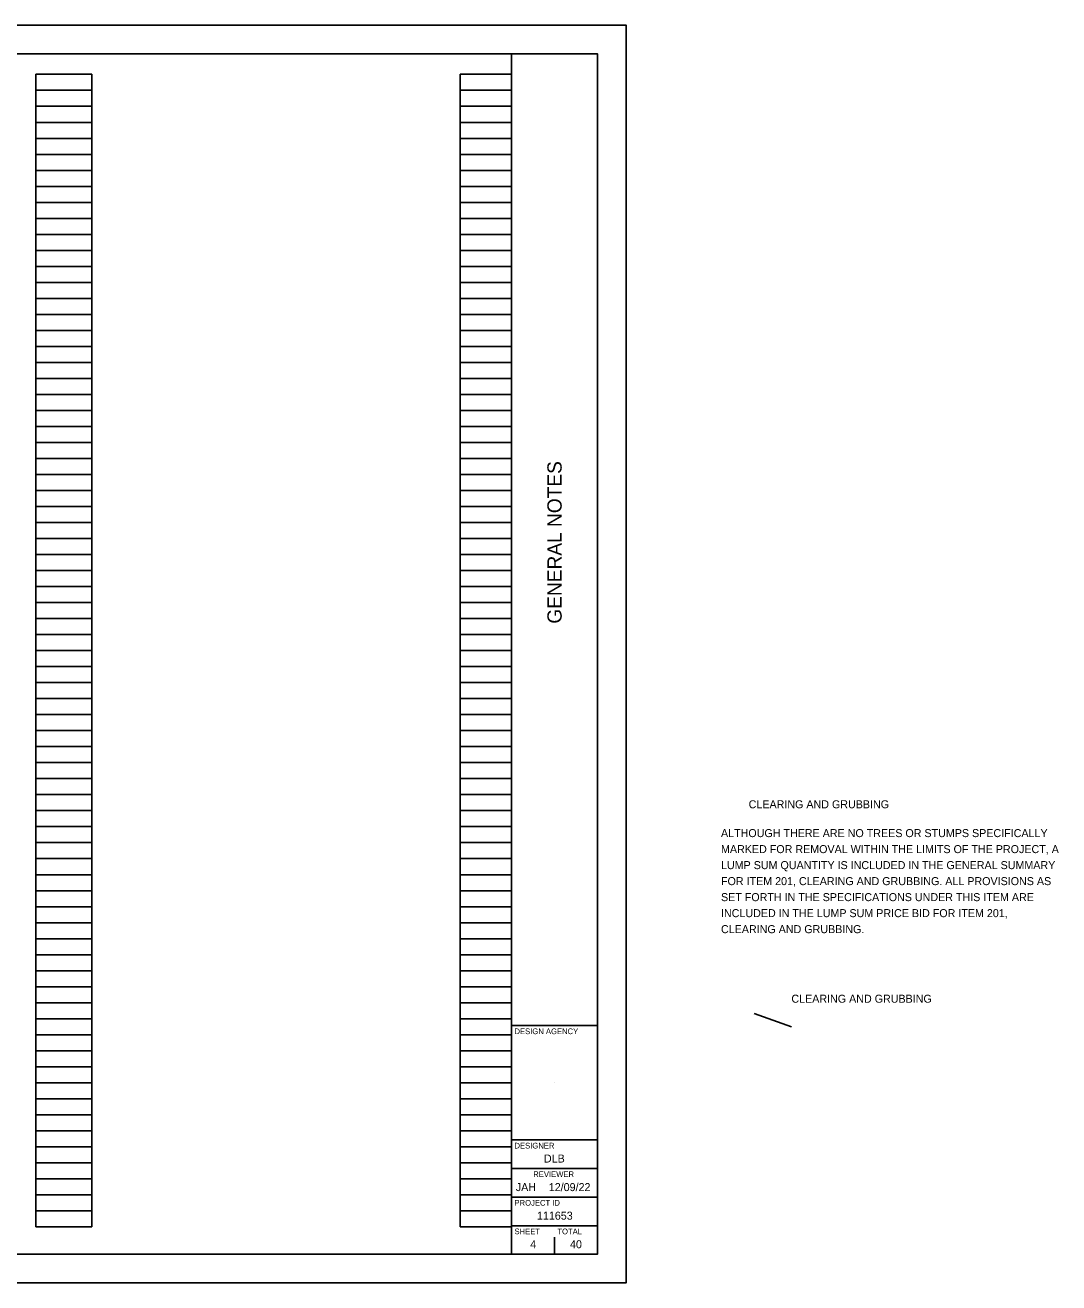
# Model space of a CAD drawing. Extents: x 0 to 41.6, y 0 to 22.
# Drawn here: x 23.49 to 41.57, y 0 to 22 of the extents above; entities that cross this region are included whole.
import ezdxf

# ---------------------------------------------------------------- set-up
doc = ezdxf.new("R2010")
doc.units = 0
for name, color, linetype in [('SC_Scratch2', 7, 'Continuous'), ('SH_Border', 7, 'Continuous'), ('SH_Cut_Line', 7, 'Continuous'), ('SH_Data', 7, 'Continuous'), ('SH_Text', 7, 'Continuous')]:
    doc.layers.add(name, color=color, linetype=linetype)

msp = doc.modelspace()

# ---------------------------------------------------------------- linework, layer by layer
at = {"layer": 'SC_Scratch2'}
for p, q in [((23.68, 0.98), (23.68, 21.14)), ((23.68, 21.14), (24.66, 21.14)), ((24.66, 0.98), (24.66, 21.14)), ((31.1, 0.98), (31.1, 21.14)), ((31.1, 21.14), (32, 21.14)), ((32, 0.98), (32, 21.14)), ((23.68, 20.86), (24.66, 20.86)), ((31.1, 20.86), (32, 20.86)), ((23.68, 20.58), (24.66, 20.58)), ((31.1, 20.58), (32, 20.58)), ((23.68, 20.3), (24.66, 20.3)), ((31.1, 20.3), (32, 20.3)), ((23.68, 20.02), (24.66, 20.02)), ((31.1, 20.02), (32, 20.02)), ((23.68, 19.74), (24.66, 19.74)), ((31.1, 19.74), (32, 19.74)), ((23.68, 19.46), (24.66, 19.46)), ((31.1, 19.46), (32, 19.46)), ((23.68, 19.18), (24.66, 19.18)), ((31.1, 19.18), (32, 19.18)), ((23.68, 18.9), (24.66, 18.9)), ((31.1, 18.9), (32, 18.9)), ((23.68, 18.62), (24.66, 18.62)), ((31.1, 18.62), (32, 18.62)), ((23.68, 18.34), (24.66, 18.34)), ((31.1, 18.34), (32, 18.34)), ((23.68, 18.06), (24.66, 18.06)), ((31.1, 18.06), (32, 18.06)), ((23.68, 17.78), (24.66, 17.78)), ((31.1, 17.78), (32, 17.78)), ((23.68, 17.5), (24.66, 17.5)), ((31.1, 17.5), (32, 17.5)), ((23.68, 17.22), (24.66, 17.22)), ((31.1, 17.22), (32, 17.22)), ((23.68, 16.94), (24.66, 16.94)), ((31.1, 16.94), (32, 16.94)), ((23.68, 16.66), (24.66, 16.66)), ((31.1, 16.66), (32, 16.66)), ((23.68, 16.38), (24.66, 16.38)), ((31.1, 16.38), (32, 16.38)), ((23.68, 16.1), (24.66, 16.1)), ((31.1, 16.1), (32, 16.1)), ((23.68, 15.82), (24.66, 15.82)), ((31.1, 15.82), (32, 15.82)), ((23.68, 15.54), (24.66, 15.54)), ((31.1, 15.54), (32, 15.54)), ((23.68, 15.26), (24.66, 15.26)), ((31.1, 15.26), (32, 15.26)), ((23.68, 14.98), (24.66, 14.98)), ((31.1, 14.98), (32, 14.98)), ((23.68, 14.7), (24.66, 14.7)), ((31.1, 14.7), (32, 14.7)), ((23.68, 14.42), (24.66, 14.42)), ((31.1, 14.42), (32, 14.42)), ((23.68, 14.14), (24.66, 14.14)), ((31.1, 14.14), (32, 14.14)), ((23.68, 13.86), (24.66, 13.86)), ((31.1, 13.86), (32, 13.86)), ((23.68, 13.58), (24.66, 13.58)), ((31.1, 13.58), (32, 13.58)), ((23.68, 13.3), (24.66, 13.3)), ((31.1, 13.3), (32, 13.3)), ((23.68, 13.02), (24.66, 13.02)), ((31.1, 13.02), (32, 13.02)), ((23.68, 12.74), (24.66, 12.74)), ((31.1, 12.74), (32, 12.74)), ((23.68, 12.46), (24.66, 12.46)), ((31.1, 12.46), (32, 12.46)), ((23.68, 12.18), (24.66, 12.18)), ((31.1, 12.18), (32, 12.18)), ((23.68, 11.9), (24.66, 11.9)), ((31.1, 11.9), (32, 11.9)), ((23.68, 11.62), (24.66, 11.62)), ((31.1, 11.62), (32, 11.62)), ((23.68, 11.34), (24.66, 11.34)), ((31.1, 11.34), (32, 11.34)), ((23.68, 11.06), (24.66, 11.06)), ((31.1, 11.06), (32, 11.06)), ((23.68, 10.78), (24.66, 10.78)), ((31.1, 10.78), (32, 10.78)), ((23.68, 10.5), (24.66, 10.5)), ((31.1, 10.5), (32, 10.5)), ((23.68, 10.22), (24.66, 10.22)), ((31.1, 10.22), (32, 10.22)), ((23.68, 9.94), (24.66, 9.94)), ((31.1, 9.94), (32, 9.94)), ((23.68, 9.66), (24.66, 9.66)), ((31.1, 9.66), (32, 9.66)), ((23.68, 9.38), (24.66, 9.38)), ((31.1, 9.38), (32, 9.38)), ((23.68, 9.1), (24.66, 9.1)), ((31.1, 9.1), (32, 9.1)), ((23.68, 8.82), (24.66, 8.82)), ((31.1, 8.82), (32, 8.82)), ((23.68, 8.54), (24.66, 8.54)), ((31.1, 8.54), (32, 8.54)), ((23.68, 8.26), (24.66, 8.26)), ((31.1, 8.26), (32, 8.26)), ((23.68, 7.98), (24.66, 7.98)), ((31.1, 7.98), (32, 7.98)), ((23.68, 7.7), (24.66, 7.7)), ((31.1, 7.7), (32, 7.7)), ((23.68, 7.42), (24.66, 7.42)), ((31.1, 7.42), (32, 7.42)), ((23.68, 7.14), (24.66, 7.14)), ((31.1, 7.14), (32, 7.14)), ((23.68, 6.86), (24.66, 6.86)), ((31.1, 6.86), (32, 6.86)), ((23.68, 6.58), (24.66, 6.58)), ((31.1, 6.58), (32, 6.58)), ((23.68, 6.3), (24.66, 6.3)), ((31.1, 6.3), (32, 6.3)), ((23.68, 6.02), (24.66, 6.02)), ((31.1, 6.02), (32, 6.02)), ((23.68, 5.74), (24.66, 5.74)), ((31.1, 5.74), (32, 5.74)), ((23.68, 5.46), (24.66, 5.46)), ((31.1, 5.46), (32, 5.46)), ((23.68, 5.18), (24.66, 5.18)), ((31.1, 5.18), (32, 5.18)), ((23.68, 4.9), (24.66, 4.9)), ((31.1, 4.9), (32, 4.9)), ((23.68, 4.62), (24.66, 4.62)), ((31.1, 4.62), (32, 4.62)), ((23.68, 4.34), (24.66, 4.34)), ((31.1, 4.34), (32, 4.34)), ((23.68, 4.06), (24.66, 4.06)), ((31.1, 4.06), (32, 4.06)), ((23.68, 3.78), (24.66, 3.78)), ((31.1, 3.78), (32, 3.78)), ((23.68, 3.5), (24.66, 3.5)), ((31.1, 3.5), (32, 3.5)), ((23.68, 3.22), (24.66, 3.22)), ((31.1, 3.22), (32, 3.22)), ((23.68, 2.94), (24.66, 2.94)), ((31.1, 2.94), (32, 2.94)), ((23.68, 2.66), (24.66, 2.66)), ((31.1, 2.66), (32, 2.66)), ((23.68, 2.38), (24.66, 2.38)), ((31.1, 2.38), (32, 2.38)), ((23.68, 2.1), (24.66, 2.1)), ((31.1, 2.1), (32, 2.1)), ((23.68, 1.82), (24.66, 1.82)), ((31.1, 1.82), (32, 1.82)), ((23.68, 1.54), (24.66, 1.54)), ((31.1, 1.54), (32, 1.54)), ((23.68, 1.26), (24.66, 1.26)), ((31.1, 1.26), (32, 1.26)), ((23.68, 0.98), (24.66, 0.98)), ((31.1, 0.98), (32, 0.98))]:
    msp.add_line(p, q, dxfattribs=at)
at = {"layer": 'SH_Border'}
msp.add_line((36.892, 4.48), (36.242, 4.713), dxfattribs=at)
at = {"layer": 'SH_Cut_Line'}
for p, q in [((32.75, 3.5), (32.75, 3.5)), ((32.375, 0.675), (32.375, 0.675)), ((32.75, 0.5), (32.75, 0.8))]:
    msp.add_line(p, q, dxfattribs=at)
at = {"layer": 'SH_Data'}
for p, q in [((32, 0.5), (32, 21.5)), ((32, 4.5), (33.5, 4.5)), ((32, 2.5), (33.5, 2.5)), ((32, 2), (33.5, 2)), ((32, 1.5), (33.5, 1.5)), ((32, 1), (33.5, 1))]:
    msp.add_line(p, q, dxfattribs=at)
msp.add_lwpolyline([(1.5, 21.5), (33.5, 21.5), (33.5, 0.5), (1.5, 0.5)], close=True, dxfattribs=at)
at = {"layer": 'SH_Text'}
msp.add_lwpolyline([(0, 0), (34, 0), (34, 22), (0, 22)], close=True, dxfattribs=at)

# ---------------------------------------------------------------- texts
at = {"layer": 'SH_Border'}
for s, p in [('CLEARING AND GRUBBING', (36.145, 8.301)), ('ALTHOUGH THERE ARE NO TREES OR STUMPS SPECIFICALLY', (35.661, 7.797)), ('MARKED FOR REMOVAL WITHIN THE LIMITS OF THE PROJECT, A', (35.661, 7.517)), ('LUMP SUM QUANTITY IS INCLUDED IN THE GENERAL SUMMARY', (35.661, 7.237)), ('FOR ITEM 201, CLEARING AND GRUBBING. ALL PROVISIONS AS', (35.661, 6.957)), ('SET FORTH IN THE SPECIFICATIONS UNDER THIS ITEM ARE', (35.661, 6.677)), ('INCLUDED IN THE LUMP SUM PRICE BID FOR ITEM 201,', (35.661, 6.397)), ('CLEARING AND GRUBBING.', (35.661, 6.117)), ('CLEARING AND GRUBBING', (36.892, 4.9))]:
    msp.add_text(s, height=0.14, dxfattribs=at).set_placement(p)
at = {"layer": 'SH_Cut_Line'}
msp.add_text('GENERAL NOTES', height=0.25, rotation=90, dxfattribs=at).set_placement((32.875, 11.531))
for s, height, p in [('DESIGN AGENCY', 0.1, (32.05, 4.35)), ('DESIGNER', 0.1, (32.05, 2.35)), ('DLB', 0.14, (32.565, 2.105)), ('REVIEWER', 0.1, (32.378, 1.85)), ('JAH', 0.14, (32.073, 1.605)), ('12/09/22', 0.14, (32.65, 1.605)), ('PROJECT ID', 0.1, (32.05, 1.35)), ('111653', 0.14, (32.443, 1.105)), ('SHEET', 0.1, (32.05, 0.85)), ('TOTAL', 0.1, (32.8, 0.85)), ('4', 0.14, (32.325, 0.605)), ('40', 0.14, (33.021, 0.605))]:
    msp.add_text(s, height=height, dxfattribs=at).set_placement(p)

doc.saveas('drawing.dxf')
